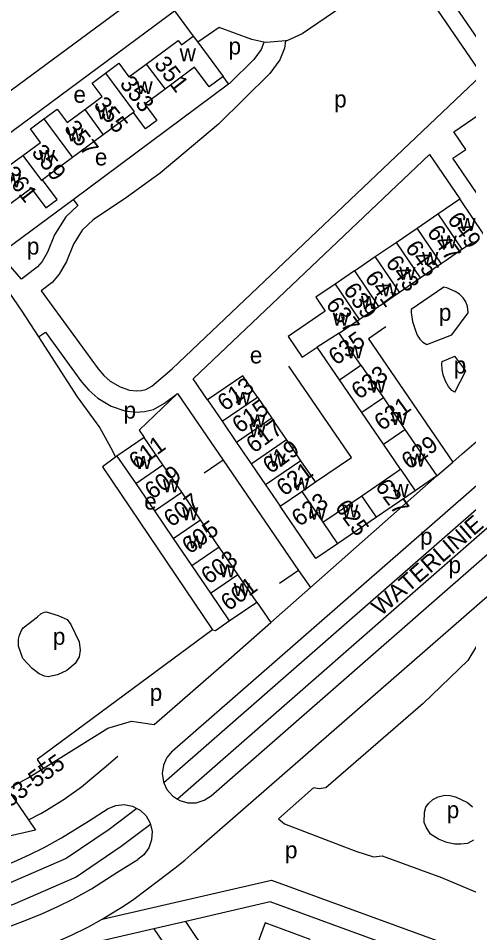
# Model space of a CAD drawing. Extents: x 154320 to 156262, y 382651 to 384180.
# Drawn here: x 155900.9 to 156007.7, y 383197.4 to 383414.4 of the extents above; entities that cross this region are included whole.
import ezdxf

# ---------------------------------------------------------------- set-up
doc = ezdxf.new("R2010")
doc.units = 0
for name, color, linetype in [('BLT_Basislijn', 7, 'Continuous'), ('BLT_Bebouwing', 7, 'Continuous'), ('BLT_Centroide', 7, 'Continuous'), ('BLT_Huisnummer', 7, 'Continuous'), ('BLT_Huisnummer_ tussenligend', 7, 'Continuous'), ('BLT_Huisnummer_reeks', 7, 'Continuous'), ('BLT_Onderverdeling_panden', 7, 'Continuous'), ('BLT_Straatnaam', 7, 'Continuous')]:
    doc.layers.add(name, color=color, linetype=linetype)

msp = doc.modelspace()

# ---------------------------------------------------------------- linework, layer by layer
at = {"layer": 'BLT_Basislijn'}
for p, q in [((155880.52, 383383.56), (155928.8, 383419.3)), ((155948.47, 383412.16), (155943.43, 383408.71)), ((155950.75, 383398.8), (155949.46, 383400.55)), ((155913.86, 383371.37), (155950.75, 383398.8)), ((155897.76, 383359.4), (155913.86, 383371.37)), ((156057.41, 383339.79), (155935.41, 383232.93)), ((155937.39, 383240.46), (156050.24, 383339.15)), ((156060.26, 383335.64), (155938.63, 383229.11)), ((156007, 383330.71), (156004.43, 383334.15)), ((155946.6, 383229.91), (156059.86, 383328.96)), ((155929.55, 383316.66), (155938.66, 383325.32)), ((155938.66, 383325.32), (155949.48, 383309.5)), ((156006.17, 383311), (156012.26, 383316.25)), ((155923.89, 383310.21), (155920.86, 383307.91)), ((155924.26, 383310.49), (155923.89, 383310.21)), ((155949.48, 383309.5), (155944.95, 383306.41)), ((155949.48, 383309.5), (155967.34, 383283.37)), ((156000.11, 383305.77), (156003.92, 383309.06)), ((156003.92, 383309.06), (156006.17, 383311)), ((155970.14, 383279.28), (156000.11, 383305.77)), ((155967.34, 383283.37), (155962.83, 383280.29)), ((155967.34, 383283.37), (155970.14, 383279.28)), ((155942.48, 383216.52), (156016.82, 383281.36)), ((155960.76, 383270.98), (155970.14, 383279.28)), ((155957.43, 383275.85), (155960.76, 383270.98)), ((155951.4, 383262.8), (155960.76, 383270.98)), ((155933.11, 383246.83), (155951.4, 383262.8)), ((155921.25, 383236.48), (155924.44, 383239.26)), ((155903.07, 383234.06), (155906.79, 383236.37)), ((155898.32, 383231.44), (155903.07, 383234.06)), ((155940.33, 383214.63), (155942.48, 383216.52)), ((155920.78, 383200.65), (155960.94, 383209.9)), ((155920.78, 383200.65), (155921.82, 383201.23)), ((155933.05, 383198.35), (155919, 383195.11)), ((155940.61, 383200.09), (155933.05, 383198.35)), ((155957.88, 383174.46), (155940.61, 383200.09))]:
    msp.add_line(p, q, dxfattribs=at)
for points in [[(155992.7, 383427.46), (156010.8, 383400.93), (155937.34, 383331.15)], [(155992.7, 383427.46), (155968.2, 383410.67), (155964.55, 383409.02), (155964.22, 383408.99)], [(156012.64, 383405.48), (156001.19, 383422.21)], [(155883.47, 383375.78), (155937.95, 383416.11), (155942.37, 383410.13)], [(155959.13, 383408.71), (155956.26, 383409.33), (155948.47, 383412.16)], [(155964.22, 383408.99), (155963.98, 383407.29), (155962.86, 383404.46), (155960.52, 383401.29), (155948.34, 383389.25), (155934.48, 383377.6), (155926.56, 383371.86), (155918.65, 383366.52), (155916.01, 383364.06), (155913.92, 383360.73), (155912.32, 383356.64), (155910.59, 383353.68), (155908.86, 383351.7), (155906.29, 383349.72), (155919.81, 383331.17), (155921.17, 383329.6), (155922.66, 383328.25), (155924.99, 383326.92), (155927.21, 383326.13), (155928.86, 383325.96), (155930.06, 383326.03), (155931.08, 383326.27), (155932.54, 383327.1), (155937.34, 383331.15)], [(155959.13, 383408.71), (155959.12, 383408.58), (155958.45, 383406.91), (155956.73, 383404.57), (155950.97, 383398.88), (155950.75, 383398.8)], [(155964.22, 383408.99), (155959.71, 383408.58), (155959.13, 383408.71)], [(156010.72, 383371.23), (156003.96, 383381.13), (156007.05, 383383.25), (156004.17, 383387.44), (156014.47, 383394.49), (156017.34, 383390.3)], [(155945.76, 383323.8), (155942.37, 383328.81), (155998.44, 383382.05), (156005.58, 383371.49)], [(155913.86, 383371.37), (155914.95, 383369.91), (155912.12, 383367.27), (155909.43, 383362.99), (155907.81, 383358.83), (155906.51, 383356.62), (155905.42, 383355.36), (155901.62, 383352.44), (155896.38, 383358.38)], [(155893.74, 383356.42), (155901.72, 383344.89), (155905.64, 383338.8)], [(156001.81, 383350.54), (155994.09, 383345.27)], [(156007.55, 383344.44), (156007.57, 383344.57), (156007.42, 383346.01), (156007.04, 383347.04), (156006.4, 383348.05), (156005.5, 383348.92), (156004.46, 383349.54), (156002.49, 383350.39), (156001.81, 383350.54)], [(155994.09, 383345.27), (155994.08, 383344.52), (155994.39, 383342.39), (155995.08, 383340.24), (155995.47, 383339.17), (155996.08, 383338.24), (155996.81, 383337.52), (155997.78, 383336.92)], [(155997.78, 383336.92), (156003.71, 383339.24), (156007.55, 383344.44)], [(155905.64, 383338.8), (155907.29, 383339.86), (155915.89, 383328.06), (155917.58, 383326.1), (155919.7, 383324.19), (155922.9, 383322.35), (155926.11, 383321.22), (155928.75, 383320.94), (155930.78, 383321.07), (155932.91, 383321.57), (155935.51, 383323.04), (155938.66, 383325.32)], [(155988.07, 383341.15), (155983.94, 383338.33), (156003.92, 383309.06)], [(155905.64, 383338.8), (155914.8, 383324.55), (155920.21, 383317.22), (155923.18, 383311.69), (155923.89, 383310.21)], [(156004.4, 383325.66), (156003.68, 383326.04), (156002.92, 383327.02), (156002.21, 383328.25), (156001.66, 383329.74), (156001.4, 383330.99), (156001.33, 383332.46), (156001.39, 383332.96)], [(156001.39, 383332.96), (156004.43, 383334.15)], [(155971.36, 383304.34), (155979.86, 383310.13), (155965.05, 383331.8)], [(156004.4, 383325.66), (156007, 383330.71)], [(155929.55, 383316.66), (155930.74, 383314.89)], [(155920.86, 383307.91), (155946.89, 383269.23)], [(155946.89, 383269.23), (155947.6, 383269.11), (155950.92, 383271.42)], [(155946.89, 383269.23), (155905.35, 383238.53), (155906.79, 383236.37)], [(156011.34, 383268.41), (156007.52, 383261.99), (155996.87, 383251.78), (155973.79, 383231.77), (155972.23, 383231.52), (155970.88, 383231.79), (155962.55, 383224.45), (155964.02, 383223.22), (155980.92, 383216.77), (155985.15, 383215.38), (155987.15, 383215.65), (156001.25, 383210.49), (156030.38, 383198.26), (156048.23, 383191.07), (156048.84, 383190.84)], [(155922.09, 383245.91), (155927.71, 383247.57), (155933.11, 383246.83)], [(155906.79, 383236.37), (155922.09, 383245.91)], [(155937.39, 383240.46), (155936.1, 383238.94), (155935.27, 383237.11), (155934.97, 383235.14), (155935.3, 383233.17), (155935.41, 383232.93)], [(155908.18, 383226.87), (155911.76, 383229.11), (155915.83, 383232.01), (155921.25, 383236.48)], [(155935.41, 383232.93), (155936.13, 383231.35), (155937.45, 383229.85), (155938.63, 383229.11)], [(155938.63, 383229.11), (155939.15, 383228.78), (155941.07, 383228.23), (155943.07, 383228.24), (155944.98, 383228.84), (155946.6, 383229.91)], [(155997.16, 383223.51), (155997.18, 383225.96), (155997.52, 383227.15), (155998.16, 383228.04), (155999.23, 383228.98), (156000.43, 383229.6), (156002.02, 383230), (156003.3, 383229.97), (156004.6, 383229.66), (156007.4, 383228.29), (156008.63, 383227.29)], [(155849.52, 383201.59), (155884.54, 383209.44), (155888.43, 383210.39), (155892.27, 383211.51), (155896.05, 383212.8), (155899.78, 383214.25), (155903.45, 383215.85), (155907.03, 383217.63), (155911.13, 383219.89), (155917.48, 383223.85), (155922.14, 383226.87)], [(155928.97, 383226.88), (155922.39, 383221.88), (155912.19, 383214.98), (155897.82, 383208.74), (155879.68, 383203.84), (155852.15, 383197.73)], [(155906.17, 383225.71), (155907.52, 383226.46)], [(155907.52, 383226.46), (155908.18, 383226.87)], [(155922.14, 383226.87), (155924.01, 383227.6), (155926, 383227.79), (155927.96, 383227.41), (155928.97, 383226.88)], [(155928.97, 383226.88), (155929.73, 383226.48), (155931.17, 383225.09), (155932.16, 383223.35), (155932.23, 383223.07)], [(155903.3, 383224.14), (155906.17, 383225.71)], [(155932.23, 383223.07), (155925.3, 383217.82), (155914.61, 383210.57), (155899.48, 383204.01), (155880.87, 383198.99), (155855.18, 383193.28)], [(155932.23, 383223.07), (155932.6, 383221.4), (155932.49, 383219.4), (155931.84, 383217.51), (155930.66, 383215.9), (155929.2, 383214.78)], [(156008.87, 383219.39), (156007.44, 383218.57), (156005.83, 383218.4), (156004.43, 383218.41), (156002.53, 383218.8), (156001.29, 383219.25), (156000.52, 383219.6), (155998.65, 383220.75), (155997.62, 383222.41), (155997.16, 383223.51)], [(155858, 383189.14), (155887.6, 383195.77), (155891.49, 383196.72), (155895.34, 383197.79), (155899.14, 383199.05), (155902.9, 383200.42), (155906.6, 383201.93), (155910.24, 383203.58), (155913.82, 383205.38), (155918.19, 383207.8), (155924.24, 383211.67), (155929.2, 383214.78)], [(155938.11, 383212.79), (155940.33, 383214.63)], [(155928.24, 383205.39), (155934.15, 383209.76), (155938.11, 383212.79)], [(155960.94, 383209.9), (156026.16, 383186.09), (156037.02, 383182.14)], [(155921.82, 383201.23), (155926.06, 383203.88), (155928.24, 383205.39)], [(156024.45, 383181.39), (155960.61, 383204.7), (155940.61, 383200.09)], [(155904.75, 383193.12), (155905.6, 383193.43), (155909.56, 383195.04), (155913.48, 383196.81), (155917.32, 383198.74), (155920.78, 383200.65)], [(155933.05, 383198.35), (155954.54, 383166.91), (155990.99, 383153.67)]]:
    msp.add_lwpolyline(points, dxfattribs=at)
msp.add_lwpolyline([(155902.04, 383269.76), (155905.39, 383272.35), (155906.32, 383273.13), (155907.1, 383273.47), (155907.5, 383273.53), (155910.29, 383272.69), (155912.42, 383271.68), (155913.29, 383270.5), (155915.26, 383266.44), (155915.57, 383264.44), (155915.29, 383262.86), (155914.32, 383261.26), (155912.41, 383259.62), (155910.13, 383258.57), (155907.92, 383258.14), (155907.07, 383258.3), (155905.84, 383258.79), (155904.16, 383260.09), (155901.91, 383262.42), (155900.9, 383265.36), (155900.93, 383267.04), (155901.18, 383267.99), (155901.62, 383269.09)], close=True, dxfattribs=at)
at = {"layer": 'BLT_Bebouwing'}
for p, q in [((155943.43, 383408.71), (155949.46, 383400.55)), ((155928.18, 383392.02), (155921.03, 383386.72)), ((155921.03, 383386.72), (155913.71, 383381.29)), ((155913.71, 383381.29), (155906.62, 383376.04)), ((156000.4, 383367.95), (156005.58, 383371.49)), ((156011.3, 383363.09), (156005.58, 383371.49)), ((155995.45, 383364.57), (156000.4, 383367.95)), ((155990.5, 383361.18), (155995.45, 383364.57)), ((155985.55, 383357.8), (155990.5, 383361.18)), ((156006.1, 383359.54), (156008.75, 383361.35)), ((156002.14, 383356.83), (156006.1, 383359.54)), ((155980.59, 383354.41), (155985.55, 383357.8)), ((156001.18, 383356.18), (156002.14, 383356.83)), ((155996.22, 383352.78), (156001.18, 383356.18)), ((155980.59, 383354.41), (155976.02, 383351.28)), ((155991.28, 383349.41), (155996.22, 383352.78)), ((155986.28, 383345.99), (155989.77, 383348.38)), ((155989.77, 383348.38), (155991.28, 383349.41)), ((155983.17, 383343.86), (155986.28, 383345.99)), ((155981.75, 383342.9), (155983.17, 383343.86)), ((155976.99, 383339.64), (155981.75, 383342.9)), ((155982.15, 383332.08), (155976.99, 383339.64)), ((155977.02, 383328.57), (155971.72, 383336.33)), ((155982.15, 383332.08), (155987.46, 383324.31)), ((155982.32, 383320.82), (155977.02, 383328.57)), ((155957.6, 383324.49), (155961.04, 383319.45)), ((155987.46, 383324.31), (155992.59, 383316.79)), ((155987.47, 383313.27), (155982.32, 383320.82)), ((155949.21, 383318.75), (155952.65, 383313.72)), ((155964.48, 383314.41), (155961.04, 383319.45)), ((155992.59, 383316.79), (156000.11, 383305.77)), ((155952.65, 383313.72), (155956.09, 383308.68)), ((155967.92, 383309.38), (155964.48, 383314.41)), ((155991.51, 383307.36), (155987.47, 383313.27)), ((155971.36, 383304.34), (155967.92, 383309.38)), ((155939.63, 383301.89), (155935.18, 383308.4)), ((155956.09, 383308.68), (155959.53, 383303.65)), ((155982.32, 383301.08), (155991.51, 383307.36)), ((156000.11, 383305.77), (155994.99, 383302.27)), ((155928.71, 383303.98), (155933.15, 383297.47)), ((155959.53, 383303.65), (155962.98, 383298.61)), ((155968.08, 383302.1), (155971.36, 383304.34)), ((155944.08, 383295.38), (155939.63, 383301.89)), ((155968.08, 383302.1), (155973.09, 383294.78)), ((155973.09, 383294.78), (155982.32, 383301.08)), ((155994.99, 383302.27), (155985.81, 383296.01)), ((155933.15, 383297.47), (155937.59, 383290.96)), ((155985.81, 383296.01), (155976.56, 383289.7)), ((155948.53, 383288.87), (155944.08, 383295.38)), ((155937.59, 383290.96), (155942.04, 383284.44)), ((155952.97, 383282.36), (155948.53, 383288.87)), ((155942.04, 383284.44), (155946.48, 383277.93)), ((155898.32, 383231.44), (155903.3, 383224.14)), ((155903.3, 383224.14), (155904.96, 383221.72)), ((155904.96, 383221.72), (155887.09, 383217.71))]:
    msp.add_line(p, q, dxfattribs=at)
for points in [[(155931.22, 383403.48), (155938.81, 383409.1), (155939.58, 383408.06), (155942.37, 383410.13)], [(155942.37, 383410.13), (155943.43, 383408.71)], [(155921.56, 383401.33), (155924.73, 383403.67), (155927.11, 383400.45), (155931.22, 383403.48)], [(155949.46, 383400.55), (155946.14, 383398.1), (155942.69, 383402.76), (155935.66, 383397.56)], [(155916.61, 383392.68), (155920.77, 383395.76), (155918.38, 383398.98), (155921.56, 383401.33)], [(155935.66, 383397.56), (155930.85, 383393.99), (155933.71, 383390.13), (155931.04, 383388.16), (155928.18, 383392.02)], [(155906.9, 383390.46), (155910.07, 383392.81), (155912.45, 383389.6), (155916.61, 383392.68)], [(155901.97, 383381.83), (155906.11, 383384.9), (155903.73, 383388.11), (155906.9, 383390.46)], [(155892.27, 383379.62), (155895.44, 383381.97), (155897.82, 383378.76), (155901.97, 383381.83)], [(155899.06, 383370.45), (155903.95, 383374.07), (155907.4, 383369.41), (155910.07, 383371.38), (155906.62, 383376.04)], [(155976.02, 383351.28), (155971.45, 383348.16), (155973.68, 383344.88), (155964.87, 383338.84), (155968.22, 383333.94), (155971.72, 383336.33)], [(155957.6, 383324.49), (155954.16, 383329.52), (155945.76, 383323.8)], [(155945.76, 383323.8), (155949.21, 383318.75)], [(155930.74, 383314.89), (155924.26, 383310.49)], [(155935.18, 383308.4), (155930.74, 383314.89)], [(155924.26, 383310.49), (155928.71, 383303.98)], [(155976.56, 383289.7), (155971.45, 383286.21), (155962.98, 383298.61)], [(155957.43, 383275.85), (155952.97, 383282.36)], [(155946.48, 383277.93), (155950.92, 383271.42)], [(155950.92, 383271.42), (155957.43, 383275.85)], [(155963.09, 383171.24), (155968.43, 383185.96), (155968.6, 383185.9), (155970.01, 383189.73), (155969.34, 383189.98), (155969.78, 383191.19), (155968.57, 383191.63), (155970.1, 383195.82), (155959.42, 383199.72), (155956.68, 383192.21), (155963.42, 383189.75)]]:
    msp.add_lwpolyline(points, dxfattribs=at)
at = {"layer": 'BLT_Onderverdeling_panden'}
for p, q in [((155931.22, 383403.48), (155935.66, 383397.56)), ((155916.61, 383392.68), (155921.03, 383386.72)), ((155906.9, 383390.46), (155913.71, 383381.29)), ((156000.4, 383367.95), (156006.1, 383359.54)), ((156001.18, 383356.18), (155995.45, 383364.57)), ((155990.5, 383361.18), (155996.22, 383352.78)), ((155991.28, 383349.41), (155985.55, 383357.8)), ((155980.59, 383354.41), (155986.28, 383345.99)), ((155976.02, 383351.28), (155981.75, 383342.9)), ((155976.99, 383339.64), (155971.72, 383336.33)), ((155977.02, 383328.57), (155982.15, 383332.08)), ((155949.21, 383318.75), (155957.6, 383324.49)), ((155987.46, 383324.31), (155982.32, 383320.82)), ((155961.04, 383319.45), (155952.65, 383313.72)), ((155987.47, 383313.27), (155992.59, 383316.79)), ((155956.09, 383308.68), (155964.48, 383314.41)), ((155967.92, 383309.38), (155959.53, 383303.65)), ((155928.71, 383303.98), (155935.18, 383308.4)), ((155991.51, 383307.36), (155994.99, 383302.27)), ((155933.15, 383297.47), (155939.63, 383301.89)), ((155962.98, 383298.61), (155968.08, 383302.1)), ((155985.81, 383296.01), (155982.32, 383301.08)), ((155937.59, 383290.96), (155944.08, 383295.38)), ((155973.09, 383294.78), (155976.56, 383289.7)), ((155948.53, 383288.87), (155942.04, 383284.44)), ((155946.48, 383277.93), (155952.97, 383282.36))]:
    msp.add_line(p, q, dxfattribs=at)
for points in [[(155921.56, 383401.33), (155928.36, 383392.14), (155928.18, 383392.02)], [(155901.97, 383381.83), (155906.38, 383375.87), (155906.62, 383376.04)]]:
    msp.add_lwpolyline(points, dxfattribs=at)

# ---------------------------------------------------------------- texts
at = {"layer": 'BLT_Centroide'}
for s, p in [('p', (155950.73, 383405.76)), ('w', (155939.13, 383404.15)), ('w', (155928.89, 383396.35)), ('e', (155913.94, 383394.3)), ('p', (155975.78, 383393.21)), ('w', (155919.52, 383390.37)), ('w', (155912.45, 383385.14)), ('w', (155905.72, 383380.07)), ('e', (155919.02, 383379.43)), ('w', (155897.64, 383374.23)), ('p', (155902.9, 383358.29)), ('p', (156000.62, 383342.57)), ('e', (155955.78, 383332.47)), ('p', (156004.14, 383330.08)), ('p', (155925.83, 383319.37)), ('e', (155930.73, 383297.78)), ('p', (155996.15, 383289.45)), ('p', (156002.92, 383282.69)), ('p', (155909.06, 383265.7)), ('p', (155932.03, 383252.39)), ('p', (156002.48, 383224.57)), ('p', (155964.12, 383215.05))]:
    msp.add_text(s, height=4, dxfattribs=at).set_placement(p)
for p in [(156005.47, 383363.89), (156000.99, 383359.77), (155996.62, 383355.83), (155991.21, 383352.32), (155987.03, 383348.38), (155982.11, 383345.37), (155975.41, 383341.43), (155978.75, 383333.67), (155984.17, 383325.57), (155952.16, 383322.61), (155955.65, 383317.36), (155989.24, 383317.86), (155955.65, 383314.96), (155960.4, 383307.99), (155993.53, 383307.99), (155928.58, 383307.43), (155935.14, 383301.88), (155966.04, 383302.36), (155989.58, 383300.83), (155939.66, 383295.28), (155970, 383295.4), (155977.65, 383295.88), (155941.19, 383288.58), (155948.51, 383281.71), (155951.92, 383277.27)]:
    msp.add_text('w', height=4, rotation=359.5, dxfattribs=at).set_placement(p)
at = {"layer": 'BLT_Huisnummer'}
for s, rotation, p in [('351', 308.0883, (155932.9, 383403.44)), ('355', 308.0883, (155918.55, 383393.78)), ('359', 308.0883, (155903.84, 383382.47)), ('649', 306.0883, (156002.46, 383366.58)), ('645', 306.0883, (155992.46, 383359.84)), ('641', 306.0883, (155982.89, 383352.73)), ('637', 306.0883, (155973.65, 383346.43)), ('635', 36.0883, (155976.29, 383331.88)), ('633', 36.0883, (155981.7, 383323.77)), ('613', 36.0883, (155949.93, 383320.98)), ('617', 36.0883, (155956.76, 383311.03)), ('611', 36.0883, (155928.95, 383307.11)), ('629', 36.0883, (155993.58, 383307.13)), ('609', 36.0883, (155932.68, 383300.08)), ('621', 36.0883, (155963.94, 383300.83)), ('627', 306.0883, (155985.38, 383303.25)), ('623', 36.0883, (155967.54, 383293.6)), ('625', 306.0883, (155975.85, 383298.35)), ('605', 36.0883, (155941.53, 383287.08)), ('601', 36.0883, (155950.74, 383273.59))]:
    msp.add_text(s, height=4, rotation=rotation, dxfattribs=at).set_placement(p)
at = {"layer": 'BLT_Huisnummer_ tussenligend'}
for s, rotation, p in [('353', 308.0883, (155924.74, 383398.75)), ('357', 308.0883, (155911.55, 383388.22)), ('361', 308.0883, (155897.08, 383377.33)), ('647', 306.0883, (155997.64, 383363.51)), ('643', 306.0883, (155987.83, 383356.33)), ('639', 306.0883, (155977.79, 383349.84)), ('631', 36.0883, (155987.14, 383316.33)), ('615', 36.0883, (155953.43, 383315.74)), ('619', 36.0883, (155960.69, 383306.12)), ('607', 36.0883, (155937.19, 383293.48)), ('603', 36.0883, (155946.05, 383279.92))]:
    msp.add_text(s, height=4, rotation=rotation, dxfattribs=at).set_placement(p)
at = {"layer": 'BLT_Huisnummer_reeks'}
msp.add_text('527-553-555', height=4, rotation=36.0883, dxfattribs=at).set_placement((155887.77, 383218.99))
at = {"layer": 'BLT_Straatnaam'}
msp.add_text('WATERLINIE', height=4, rotation=40.9083, dxfattribs=at).set_placement((155986.84, 383272.37))

doc.saveas('drawing.dxf')
